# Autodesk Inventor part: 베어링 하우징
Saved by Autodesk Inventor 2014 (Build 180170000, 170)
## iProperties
Created: 2026-01
Part Number: 베어링 하우징
Material: 일반
Document SubType Name: Modeling
Designer: dg
Density: 1 g/cm^3
Appearance: 기본값
Author: dg
Author: jhkim
Creation Date: 2026-01-09
Sending System: Autodesk Inventor 2026
Preprocessor: ST-DEVELOPER v20.1
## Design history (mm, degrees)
node "베어링 하우징1"
node "솔리드1"
node "기준1"
